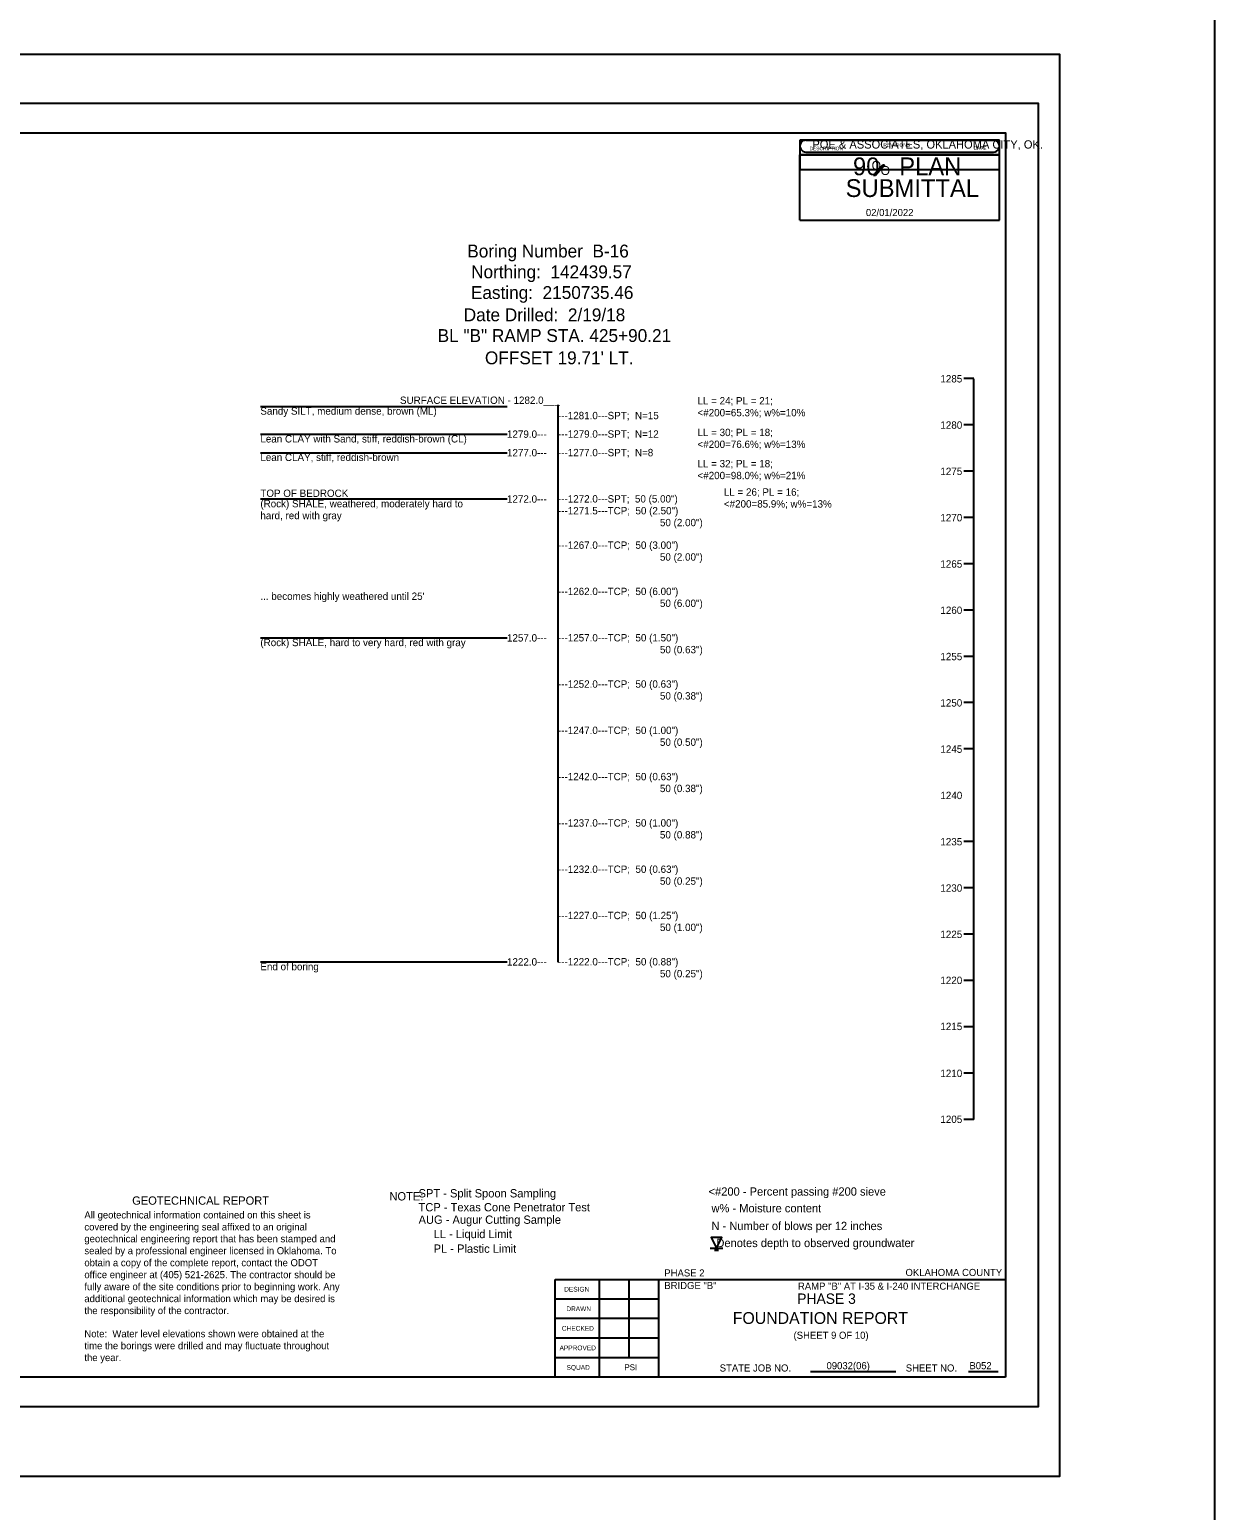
# Model space of a CAD drawing. Extents: x 2150162 to 2150245, y 143729 to 143865.
# Drawn here: x 2150225.25 to 2150245.24, y 143761.23 to 143786.22 of the extents above; entities that cross this region are included whole.
import ezdxf

# ---------------------------------------------------------------- set-up
doc = ezdxf.new("R2010")
doc.units = 0
for name, color, linetype in [('Default', 7, 'Continuous'), ('S', 7, 'Continuous'), ('SHT_Plot_Shape_Full', 7, 'Continuous'), ('SHT_Plot_Shape_Half', 7, 'Continuous'), ('SHT_Sheet_Border', 7, 'Continuous'), ('SHT_Stamp_90_Submit', 7, 'Continuous'), ('SHT_Stamp_Rev_Block', 7, 'Continuous'), ('SHT_Standard_Sheet_Lines', 7, 'Continuous'), ('SHT_Standard_Sheet_Txt', 7, 'Continuous'), ('T', 7, 'Continuous'), ('T-Title', 7, 'Continuous'), ('Text', 7, 'Continuous')]:
    doc.layers.add(name, color=color, linetype=linetype)

# ---------------------------------------------------------------- blocks, each defined once
blk = doc.blocks.new('DGRFC_WTLEV1')
at = {"layer": 'Default'}
for points in [[(-0.0127, 0), (0.0127, 0)], [(0, 0), (0.0106, 0.0212), (-0.0106, 0.0212), (0, 0)], [(-0.0042, -0.0042), (0.0042, -0.0042)]]:
    blk.add_lwpolyline(points, dxfattribs=at)

msp = doc.modelspace()

# ---------------------------------------------------------------- linework, layer by layer
at = {"layer": 'Default'}
msp.add_line((2150241.18, 143767.83), (2150241.18, 143780.33), dxfattribs=at)
for points in [[(2150241.18, 143780.331), (2150241.013, 143780.331)], [(2150229.14, 143779.863), (2150233.307, 143779.863)], [(2150234.158, 143779.89), (2150234.158, 143770.482)], [(2150229.14, 143779.394), (2150233.307, 143779.394)], [(2150241.18, 143779.55), (2150241.013, 143779.55)], [(2150229.14, 143779.081), (2150233.307, 143779.081)], [(2150241.18, 143778.769), (2150241.013, 143778.769)], [(2150241.18, 143778.769), (2150241.013, 143778.769)], [(2150229.14, 143778.3), (2150233.307, 143778.3)], [(2150241.18, 143777.988), (2150241.013, 143777.988)], [(2150241.18, 143777.206), (2150241.013, 143777.206)], [(2150241.18, 143776.425), (2150241.013, 143776.425)], [(2150229.14, 143775.956), (2150233.307, 143775.956)], [(2150241.18, 143775.644), (2150241.013, 143775.644)], [(2150241.18, 143774.863), (2150241.013, 143774.863)], [(2150241.18, 143774.081), (2150241.013, 143774.081)], [(2150241.18, 143772.517), (2150241.013, 143772.517)], [(2150241.18, 143771.736), (2150241.013, 143771.736)], [(2150241.18, 143770.955), (2150241.013, 143770.955)], [(2150229.14, 143770.488), (2150233.307, 143770.488)], [(2150241.18, 143770.174), (2150241.013, 143770.174)], [(2150241.18, 143769.392), (2150241.013, 143769.392)], [(2150241.18, 143768.611), (2150241.013, 143768.611)], [(2150241.18, 143767.83), (2150241.013, 143767.83)]]:
    msp.add_lwpolyline(points, dxfattribs=at)
at = {"layer": 'S'}
msp.add_lwpolyline([(2150203.404, 143865.061), (2150245.24, 143865.061), (2150245.24, 143729.315), (2150203.404, 143729.315)], close=True, dxfattribs=at)
at = {"layer": 'SHT_Plot_Shape_Full'}
msp.add_lwpolyline([(2150206.628, 143785.804), (2150242.628, 143785.804), (2150242.628, 143761.804), (2150206.628, 143761.804)], close=True, dxfattribs=at)
at = {"layer": 'SHT_Plot_Shape_Half'}
msp.add_lwpolyline([(2150208.265, 143784.979), (2150242.265, 143784.979), (2150242.265, 143762.979), (2150208.265, 143762.979)], close=True, dxfattribs=at)
at = {"layer": 'SHT_Sheet_Border'}
for p, q in [((2150234.115, 143763.479), (2150234.115, 143765.129)), ((2150234.115, 143765.129), (2150241.715, 143765.129)), ((2150235.865, 143763.479), (2150235.865, 143765.13))]:
    msp.add_line(p, q, dxfattribs=at)
msp.add_lwpolyline([(2150241.715, 143763.479), (2150210.215, 143763.479), (2150210.215, 143784.479), (2150241.715, 143784.479)], close=True, dxfattribs=at)
at = {"layer": 'SHT_Stamp_90_Submit'}
for p, q in [((2150238.346, 143784.355), (2150241.512, 143784.355)), ((2150238.246, 143784.105), (2150241.612, 143784.105)), ((2150238.246, 143783.006), (2150238.246, 143784.105)), ((2150238.346, 143784.155), (2150241.512, 143784.155)), ((2150241.612, 143783.006), (2150241.612, 143784.105)), ((2150239.489, 143783.767), (2150239.645, 143783.939)), ((2150239.507, 143783.767), (2150239.662, 143783.939)), ((2150239.512, 143783.767), (2150239.667, 143783.939)), ((2150239.52, 143783.767), (2150239.675, 143783.939)), ((2150239.645, 143783.939), (2150239.675, 143783.939)), ((2150239.489, 143783.767), (2150239.52, 143783.767)), ((2150238.246, 143783.006), (2150241.612, 143783.006))]:
    msp.add_line(p, q, dxfattribs=at)
for centre, start, end in [((2150238.346, 143784.255), 89.9952, 270), ((2150241.512, 143784.255), 270, 90.0048)]:
    msp.add_arc(centre, 0.1, start, end, dxfattribs=at)
at = {"layer": 'SHT_Stamp_Rev_Block'}
for p, q in [((2150238.246, 143784.355), (2150238.246, 143783.855)), ((2150241.612, 143784.355), (2150238.246, 143784.355)), ((2150241.612, 143783.855), (2150241.612, 143784.355)), ((2150241.612, 143784.105), (2150238.246, 143784.105)), ((2150241.612, 143783.855), (2150238.246, 143783.855))]:
    msp.add_line(p, q, dxfattribs=at)
at = {"layer": 'SHT_Standard_Sheet_Lines'}
for p, q in [((2150234.865, 143763.479), (2150234.865, 143765.13)), ((2150235.365, 143763.809), (2150235.365, 143765.13)), ((2150238.426, 143763.575), (2150239.866, 143763.575)), ((2150241.09, 143763.575), (2150241.593, 143763.575))]:
    msp.add_line(p, q, dxfattribs=at)
for points in [[(2150235.865, 143764.799), (2150234.115, 143764.799)], [(2150235.865, 143764.469), (2150234.115, 143764.469)], [(2150235.865, 143764.139), (2150234.115, 143764.139)], [(2150235.865, 143763.809), (2150234.115, 143763.809)]]:
    msp.add_lwpolyline(points, dxfattribs=at)

# ---------------------------------------------------------------- block references
at = {"layer": 'Default', "xscale": 8.503919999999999, "yscale": 8.503919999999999}
msp.add_blockref('DGRFC_WTLEV1', (2150236.837, 143765.657), dxfattribs=at)

# ---------------------------------------------------------------- texts
at = {"layer": 'Default'}
for s, height, p in [('Boring Number  B-16', 0.217, (2150232.632, 143782.375)), ('Northing:  142439.57', 0.217, (2150232.697, 143782.025)), ('Easting:  2150735.46', 0.217, (2150232.693, 143781.675)), ('Date Drilled:  2/19/18', 0.217, (2150232.572, 143781.299)), ('BL "B" RAMP STA. 425+90.21', 0.217, (2150232.132, 143780.949)), ("OFFSET 19.71' LT.", 0.217, (2150232.93, 143780.573)), ('1285', 0.124, (2150240.616, 143780.266)), ('SURFACE ELEVATION - 1282.0___', 0.124, (2150231.496, 143779.904)), ('LL = 24; PL = 21;', 0.124, (2150236.517, 143779.895)), ('Sandy SILT, medium dense, brown (ML)', 0.124, (2150229.14, 143779.722)), ('---1281.0---SPT;  N=15', 0.124, (2150234.162, 143779.646)), ('<#200=65.3%; w%=10%', 0.124, (2150236.517, 143779.695)), ('1280', 0.124, (2150240.616, 143779.485)), ('Lean CLAY with Sand, stiff, reddish-brown (CL)', 0.124, (2150229.14, 143779.253)), ('1279.0---', 0.124, (2150233.302, 143779.332)), ('---1279.0---SPT;  N=12', 0.124, (2150234.162, 143779.334)), ('LL = 30; PL = 18;', 0.124, (2150236.517, 143779.361)), ('1277.0---', 0.124, (2150233.302, 143779.019)), ('---1277.0---SPT;  N=8', 0.124, (2150234.162, 143779.021)), ('<#200=76.6%; w%=13%', 0.124, (2150236.517, 143779.161)), ('Lean CLAY, stiff, reddish-brown', 0.124, (2150229.14, 143778.941)), ('LL = 32; PL = 18;', 0.124, (2150236.517, 143778.834)), ('<#200=98.0%; w%=21%', 0.124, (2150236.517, 143778.634)), ('1275', 0.124, (2150240.616, 143778.704)), ('TOP OF BEDROCK', 0.124, (2150229.14, 143778.334)), ('1272.0---', 0.124, (2150233.302, 143778.238)), ('---1272.0---SPT;  50 (5.00")', 0.124, (2150234.162, 143778.24)), ('LL = 26; PL = 16;', 0.124, (2150236.962, 143778.355)), ('(Rock) SHALE, weathered, moderately hard to', 0.124, (2150229.14, 143778.159)), ('---1271.5---TCP;  50 (2.50")', 0.124, (2150234.162, 143778.04)), ('<#200=85.9%; w%=13%', 0.124, (2150236.962, 143778.155)), ('hard, red with gray', 0.124, (2150229.14, 143777.959)), ('50 (2.00")', 0.124, (2150235.883, 143777.84)), ('1270', 0.124, (2150240.616, 143777.922)), ('---1267.0---TCP;  50 (3.00")', 0.124, (2150234.162, 143777.459)), ('50 (2.00")', 0.124, (2150235.883, 143777.259)), ('1265', 0.124, (2150240.616, 143777.141)), ("... becomes highly weathered until 25'", 0.124, (2150229.14, 143776.597)), ('---1262.0---TCP;  50 (6.00")', 0.124, (2150234.162, 143776.678)), ('50 (6.00")', 0.124, (2150235.883, 143776.478)), ('1260', 0.124, (2150240.616, 143776.36)), ('(Rock) SHALE, hard to very hard, red with gray', 0.124, (2150229.14, 143775.816)), ('1257.0---', 0.124, (2150233.302, 143775.894)), ('---1257.0---TCP;  50 (1.50")', 0.124, (2150234.162, 143775.896)), ('50 (0.63")', 0.124, (2150235.883, 143775.696)), ('1255', 0.124, (2150240.616, 143775.579)), ('---1252.0---TCP;  50 (0.63")', 0.124, (2150234.162, 143775.115)), ('50 (0.38")', 0.124, (2150235.883, 143774.915)), ('1250', 0.124, (2150240.616, 143774.797)), ('---1247.0---TCP;  50 (1.00")', 0.124, (2150234.162, 143774.334)), ('50 (0.50")', 0.124, (2150235.883, 143774.134)), ('1245', 0.124, (2150240.616, 143774.016)), ('---1242.0---TCP;  50 (0.63")', 0.124, (2150234.162, 143773.553)), ('50 (0.38")', 0.124, (2150235.883, 143773.353)), ('1240', 0.124, (2150240.616, 143773.235)), ('---1237.0---TCP;  50 (1.00")', 0.124, (2150234.162, 143772.771)), ('50 (0.88")', 0.124, (2150235.883, 143772.571)), ('1235', 0.124, (2150240.616, 143772.454)), ('---1232.0---TCP;  50 (0.63")', 0.124, (2150234.162, 143771.99)), ('50 (0.25")', 0.124, (2150235.883, 143771.79)), ('1230', 0.124, (2150240.616, 143771.672)), ('---1227.0---TCP;  50 (1.25")', 0.124, (2150234.162, 143771.209)), ('50 (1.00")', 0.124, (2150235.883, 143771.009)), ('1225', 0.124, (2150240.616, 143770.891)), ('End of boring', 0.124, (2150229.14, 143770.347)), ('1222.0---', 0.124, (2150233.302, 143770.426)), ('---1222.0---TCP;  50 (0.88")', 0.124, (2150234.162, 143770.428)), ('50 (0.25")', 0.124, (2150235.883, 143770.228)), ('1220', 0.124, (2150240.616, 143770.115)), ('1215', 0.124, (2150240.616, 143769.337)), ('1210', 0.124, (2150240.616, 143768.546)), ('1205', 0.124, (2150240.616, 143767.77))]:
    msp.add_text(s, height=height, dxfattribs=at).set_placement(p)
at = {"layer": 'Defpoints'}
msp.add_text('PHASE 3', height=0.175, dxfattribs=at).set_placement((2150238.2, 143764.717))
at = {"layer": 'SHT_Stamp_90_Submit'}
for s, height, p in [('POE & ASSOCIATES, OKLAHOMA CITY, OK.', 0.14, (2150238.456, 143784.213)), ('90   PLAN', 0.3, (2150239.141, 143783.763)), ('O', 0.153, (2150239.455, 143783.852)), ('O', 0.153, (2150239.607, 143783.767)), ('SUBMITTAL', 0.3, (2150239.017, 143783.396)), ('02/01/2022', 0.12, (2150239.359, 143783.074))]:
    msp.add_text(s, height=height, dxfattribs=at).set_placement(p)
at = {"layer": 'SHT_Stamp_Rev_Block'}
for s, height, p in [('DESCRIPTION', 0.05999, (2150238.406, 143784.184)), ('REVISIONS', 0.06, (2150239.654, 143784.243)), ('DATE', 0.06, (2150241.175, 143784.188))]:
    msp.add_text(s, height=height, dxfattribs=at).set_placement(p)
at = {"layer": 'SHT_Standard_Sheet_Txt'}
for s, height, p in [('DESIGN', 0.08, (2150234.267, 143764.924)), ('DRAWN', 0.08, (2150234.303, 143764.594)), ('CHECKED', 0.08, (2150234.228, 143764.264)), ('APPROVED', 0.08, (2150234.189, 143763.934)), ('SQUAD', 0.08, (2150234.307, 143763.604)), ('STATE JOB NO.', 0.12, (2150236.892, 143763.575)), ('SHEET NO. ', 0.12, (2150240.032, 143763.575))]:
    msp.add_text(s, height=height, dxfattribs=at).set_placement(p)
at = {"layer": 'T'}
for s, height, p in [('PHASE 2', 0.12, (2150235.957, 143765.179)), ('OKLAHOMA COUNTY', 0.12, (2150240.027, 143765.187)), ('BRIDGE "B"', 0.12, (2150235.957, 143764.967)), ('RAMP "B" AT I-35 & I-240 INTERCHANGE', 0.12, (2150238.212, 143764.956)), ('(SHEET 9 OF 10)', 0.12, (2150238.138, 143764.127)), ('PSI', 0.1, (2150235.284, 143763.597)), ('09032(06)', 0.12, (2150238.694, 143763.614)), ('B052', 0.12, (2150241.106, 143763.614))]:
    msp.add_text(s, height=height, dxfattribs=at).set_placement(p)
at = {"layer": 'T-Title'}
msp.add_text('FOUNDATION REPORT', height=0.2, dxfattribs=at).set_placement((2150237.112, 143764.378))
at = {"layer": 'Text'}
for s, height, p in [('    SPT - Split Spoon Sampling', 0.14, (2150231.602, 143766.513)), (' <#200 - Percent passing #200 sieve', 0.14, (2150236.652, 143766.543)), ('GEOTECHNICAL REPORT', 0.14, (2150226.977, 143766.39)), ('NOTE:', 0.14, (2150231.318, 143766.462)), ('    TCP - Texas Cone Penetrator Test', 0.14, (2150231.602, 143766.278)), ('w% - Moisture content', 0.14, (2150236.753, 143766.261)), ('All geotechnical information contained on this sheet is ', 0.12, (2150226.17, 143766.158)), ('    AUG - Augur Cutting Sample', 0.14, (2150231.602, 143766.068)), ('covered by the engineering seal affixed to an original ', 0.12, (2150226.17, 143765.956)), ('geotechnical engineering report that has been stamped and ', 0.12, (2150226.17, 143765.756)), (' LL - Liquid Limit', 0.14, (2150232.012, 143765.826)), ('N - Number of blows per 12 inches', 0.14, (2150236.753, 143765.962)), ('sealed by a professional engineer licensed in Oklahoma. To ', 0.12, (2150226.17, 143765.554)), (' PL - Plastic Limit', 0.14, (2150232.012, 143765.579)), ('    Denotes depth to observed groundwater', 0.14, (2150236.628, 143765.675)), ('obtain a copy of the complete report, contact the ODOT ', 0.12, (2150226.17, 143765.352)), ('office engineer at (405) 521-2625. The contractor should be ', 0.12, (2150226.17, 143765.15)), ('fully aware of the site conditions prior to beginning work. Any ', 0.12, (2150226.17, 143764.948)), ('additional geotechnical information which may be desired is ', 0.12, (2150226.17, 143764.746)), ('the responsibility of the contractor.', 0.12, (2150226.17, 143764.544)), ('Note:  Water level elevations shown were obtained at the ', 0.12, (2150226.17, 143764.153)), ('time the borings were drilled and may fluctuate throughout ', 0.12, (2150226.17, 143763.951)), ('the year.', 0.12, (2150226.17, 143763.751))]:
    msp.add_text(s, height=height, dxfattribs=at).set_placement(p)

doc.saveas('drawing.dxf')
